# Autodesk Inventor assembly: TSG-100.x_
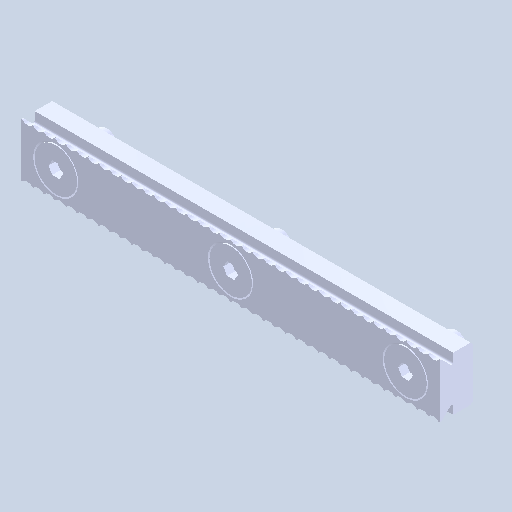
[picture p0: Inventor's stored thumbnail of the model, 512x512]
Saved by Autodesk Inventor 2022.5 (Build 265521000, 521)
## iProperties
Created: 2024-05
Part Number: TSG-100.x_
Document SubType Name: Assembly
Designer: ImaoCorp
Author: ImaoCorp
Sending System: SOLIDWORKS 2022-2022290
MC: AMD64
MC_MODEL: Intel64 Family 6 Model 60 Stepping 3, GenuineIntel
OS: Windows_NT
FRU: Parasolid Version 33.1, build 260,  4-25-2022
FORMAT: text
GUISE: transmit
KEY: FILETSG-100.x_t
DATE: Mon May 20 16:28:10 2024
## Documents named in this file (5)
- X:\14_SW2022-Inv2022\保留中\mitee-bite\データ\tsg-100\TSG-100.x_.iam
- X:\14_SW2022-Inv2022\保留中\mitee-bite\データ\tsg-100\TSG-100_01.ipt
- X:\14_SW2022-Inv2022\保留中\mitee-bite\データ\tsg-100\TSG-100_02.ipt
- X:\14_SW2022-Inv2022\保留中\mitee-bite\データ\tsg-100\TSG-100_03.ipt
- X:\14_SW2022-Inv2022\保留中\mitee-bite\データ\tsg-100\TSG-100_04.ipt
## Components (4 placed, 4 different names)
1. TSG-100_01
2. TSG-100_02
3. TSG-100_03
4. TSG-100_04
